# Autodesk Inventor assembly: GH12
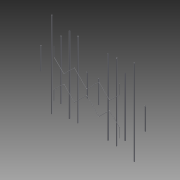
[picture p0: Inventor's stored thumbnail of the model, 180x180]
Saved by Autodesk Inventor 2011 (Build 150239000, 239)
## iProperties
Created: 2014-02
Part Number: GH12
Document SubType Name: Assembly
Designer: Evgeny
Author: Evgeny
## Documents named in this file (8)
- D:\Old Computer\Евгений\Autodesk\Projects\Antenna\GH12\GH12.iam
- D:\Old Computer\Евгений\Autodesk\Projects\Antenna\GH12\L1.ipt
- D:\Old Computer\Евгений\Autodesk\Projects\Antenna\GH12\L2.ipt
- D:\Old Computer\Евгений\Autodesk\Projects\Antenna\GH12\L3.ipt
- D:\Old Computer\Евгений\Autodesk\Projects\Antenna\GH12\L4.ipt
- D:\Old Computer\Евгений\Autodesk\Projects\Antenna\GH12\L5.ipt
- D:\Old Computer\Евгений\Autodesk\Projects\Antenna\GH12\L6.ipt
- D:\Old Computer\Евгений\Autodesk\Projects\Antenna\GH12\Ant1.ipt
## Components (14 placed, 7 different names)
1. L1:1 — Совмещение:1, Заподлицо:1, Заподлицо:2, Заподлицо:4, Совмещение:14, Заподлицо:6, Заподлицо:8, Заподлицо:10
2. L1:2 — Совмещение:2, Совмещение:3, Заподлицо:1, Совмещение:4
3. L2:1 — Совмещение:6, Совмещение:7, Заподлицо:2, Заподлицо:3
4. L2:2 — Совмещение:8, Совмещение:9, Заподлицо:3
5. L3:1 — Совмещение:10, Совмещение:11, Заподлицо:4, Заподлицо:5
6. L3:2 — Совмещение:12, Совмещение:13, Заподлицо:5
7. L4:1 — Совмещение:15, Совмещение:16, Заподлицо:7
8. L4:2 — Совмещение:17, Совмещение:18, Заподлицо:6, Заподлицо:7
9. L5:1 — Совмещение:19, Совмещение:20, Заподлицо:8, Заподлицо:9
10. L5:2 — Совмещение:21, Совмещение:22, Заподлицо:9
11. L6:1 — Совмещение:23, Совмещение:24, Заподлицо:10, Заподлицо:11
12. L6:2 — Совмещение:25, Совмещение:26, Заподлицо:11
13. Ant1:1 — Совмещение:27, Совмещение:28, Совмещение:29, Совмещение:30, Совмещение:34
14. Ant1:2 — Совмещение:31, Совмещение:32, Совмещение:33, Совмещение:34
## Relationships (44: Mate 33, Flush 11)
- Совмещение:1 [Mate]: L1:1
- Совмещение:2 [Mate]: L1:2
- Совмещение:3 [Mate]: L1:2
- Заподлицо:1 [Flush]: L1:1 ↔ L1:2
- Совмещение:4 [Mate]: L1:2
- Совмещение:6 [Mate]: L2:1
- Совмещение:7 [Mate]: L2:1
- Совмещение:8 [Mate]: L2:2
- Совмещение:9 [Mate]: L2:2
- Заподлицо:2 [Flush]: L1:1 ↔ L2:1
- Заподлицо:3 [Flush]: L2:1 ↔ L2:2
- Совмещение:10 [Mate]: L3:1
- Совмещение:11 [Mate]: L3:1
- Заподлицо:4 [Flush]: L1:1 ↔ L3:1
- Совмещение:12 [Mate]: L3:2
- Совмещение:13 [Mate]: L3:2
- Заподлицо:5 [Flush]: L3:1 ↔ L3:2
- Совмещение:14 [Mate]: L1:1
- Совмещение:15 [Mate]: L4:1
- Совмещение:16 [Mate]: L4:1
- Совмещение:17 [Mate]: L4:2
- Совмещение:18 [Mate]: L4:2
- Заподлицо:6 [Flush]: L1:1 ↔ L4:2
- Заподлицо:7 [Flush]: L4:1 ↔ L4:2
- Совмещение:19 [Mate]: L5:1
- Совмещение:20 [Mate]: L5:1
- Совмещение:21 [Mate]: L5:2
- Совмещение:22 [Mate]: L5:2
- Заподлицо:8 [Flush]: L1:1 ↔ L5:1
- Заподлицо:9 [Flush]: L5:1 ↔ L5:2
- Совмещение:23 [Mate]: L6:1
- Совмещение:24 [Mate]: L6:1
- Совмещение:25 [Mate]: L6:2
- Совмещение:26 [Mate]: L6:2
- Совмещение:27 [Mate]: Ant1:1
- Совмещение:28 [Mate]: Ant1:1
- Совмещение:29 [Mate]: Ant1:1
- Совмещение:30 [Mate]: Ant1:1
- Совмещение:31 [Mate]: Ant1:2
- Совмещение:32 [Mate]: Ant1:2
- Совмещение:33 [Mate]: Ant1:2
- Совмещение:34 [Mate]: Ant1:1 ↔ Ant1:2
- Заподлицо:10 [Flush]: L1:1 ↔ L6:1
- Заподлицо:11 [Flush]: L6:1 ↔ L6:2
